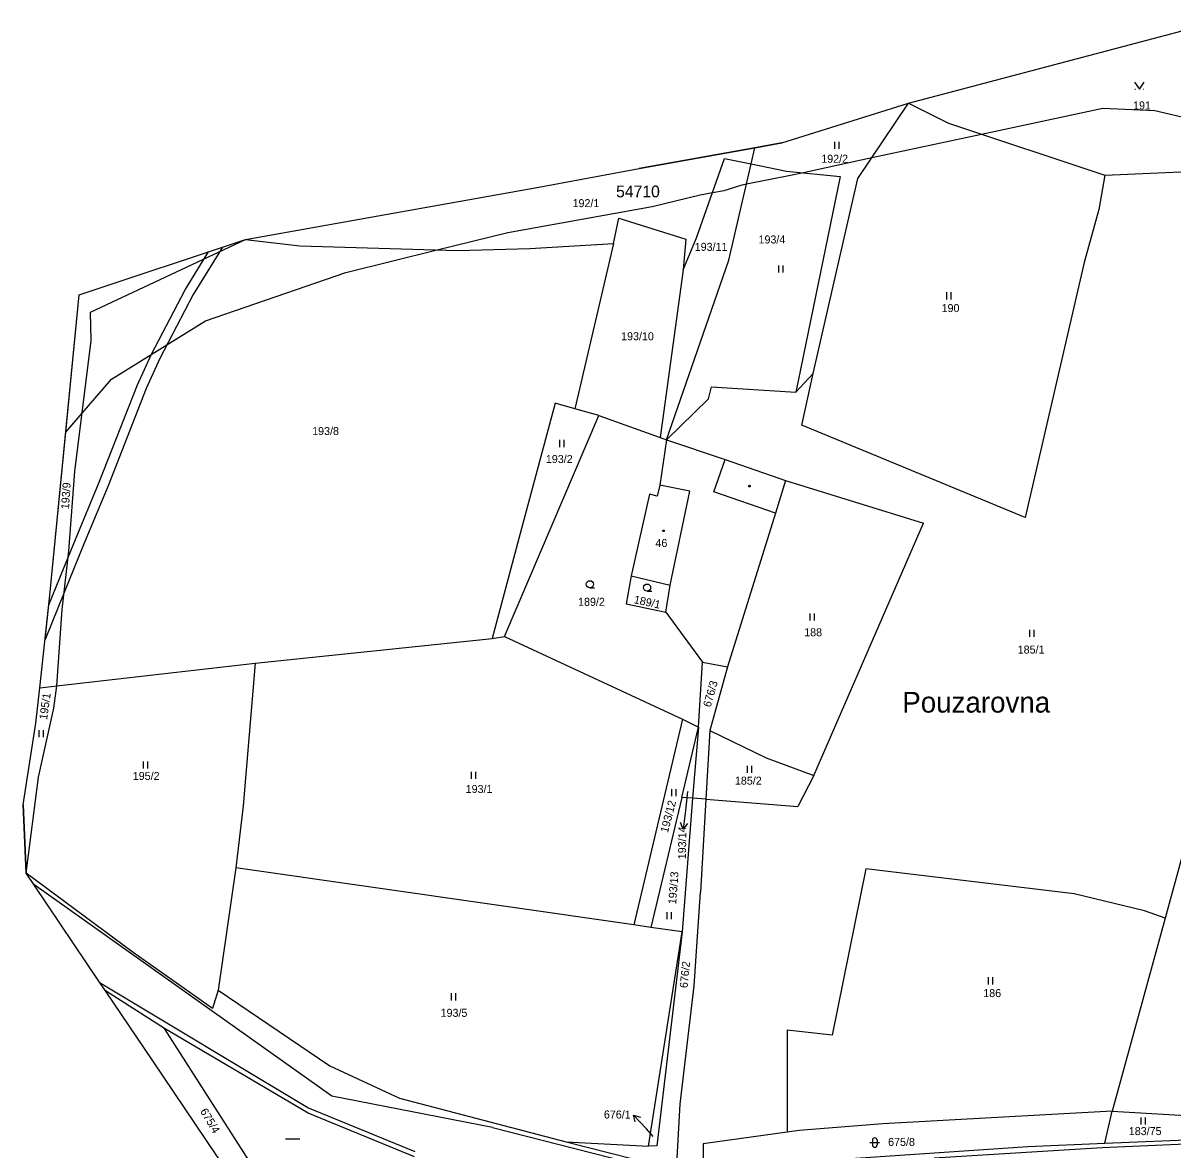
# Model space of a CAD drawing. Extents: x -747333 to -745433, y -1133152 to -1130600.
# Drawn here: x -747275.7 to -747031.5, y -1132285.5 to -1132046.2 of the extents above; entities that cross this region are included whole.
import ezdxf

# ---------------------------------------------------------------- set-up
doc = ezdxf.new("R2010")
doc.units = 0
for name, color, linetype in [('Vrstva 1', 7, 'Continuous'), ('Vrstva 13', 7, 'Continuous'), ('Vrstva 15', 7, 'Continuous'), ('Vrstva 16', 7, 'Continuous'), ('Vrstva 18', 7, 'Continuous'), ('Vrstva 19', 7, 'Continuous'), ('Vrstva 25', 7, 'Continuous'), ('Vrstva 3', 7, 'Continuous'), ('Vrstva 30', 7, 'Continuous'), ('Vrstva 37', 7, 'Continuous'), ('Vrstva 4', 7, 'Continuous'), ('Vrstva 52', 7, 'Continuous'), ('Vrstva 53', 7, 'Continuous'), ('Vrstva 6', 7, 'Continuous')]:
    doc.layers.add(name, color=color, linetype=linetype)

msp = doc.modelspace()

# ---------------------------------------------------------------- linework, layer by layer
at = {"layer": 'Vrstva 1'}
for points in [[(-747098.41, -1132079.17), (-747087.7, -1132063.18)], [(-747087.7, -1132063.18), (-747079.15, -1132067.45)], [(-747079.15, -1132067.45), (-747046.01, -1132078.5)], [(-747121.11, -1132076.06), (-747120.33, -1132072.66)], [(-747125.84, -1132096.55), (-747121.11, -1132076.06)], [(-747046.01, -1132078.5), (-747029.81, -1132077.77)], [(-747107.91, -1132120.57), (-747098.41, -1132079.17)], [(-747139.05, -1132134.66), (-747125.84, -1132096.55)], [(-747111.59, -1132124.55), (-747107.91, -1132120.57)], [(-747130.15, -1132125.95), (-747129.49, -1132123.44)], [(-747129.49, -1132123.44), (-747111.59, -1132124.55)], [(-747162.69, -1132126.85), (-747170.13, -1132154.54)], [(-747158.5, -1132128.05), (-747162.69, -1132126.85)], [(-747139.05, -1132134.66), (-747130.15, -1132125.95)], [(-747153.41, -1132129.5), (-747158.5, -1132128.05)], [(-747173.44, -1132176.4), (-747153.41, -1132129.5)], [(-747153.41, -1132129.5), (-747140.38, -1132134.18)], [(-747140.38, -1132134.18), (-747139.05, -1132134.66)], [(-747139.05, -1132134.66), (-747140.45, -1132144.31)], [(-747139.05, -1132134.66), (-747126.6, -1132138.82)], [(-747126.6, -1132138.82), (-747113.79, -1132143.31)], [(-747113.79, -1132143.31), (-747115.93, -1132150.23)], [(-747113.79, -1132143.31), (-747084.48, -1132152.35)], [(-747142.66, -1132146.22), (-747146.56, -1132163.53)], [(-747141.04, -1132146.66), (-747142.66, -1132146.22)], [(-747140.45, -1132144.31), (-747141.04, -1132146.66)], [(-747115.93, -1132150.23), (-747126.13, -1132182.86)], [(-747107.77, -1132205.94), (-747084.48, -1132152.35)], [(-747170.13, -1132154.54), (-747176.09, -1132176.86)], [(-747146.56, -1132163.53), (-747147.61, -1132169.51)], [(-747146.56, -1132163.53), (-747138.31, -1132165.52)], [(-747139.22, -1132171.24), (-747138.31, -1132165.52)], [(-747014.12, -1132166.6), (-747033.2, -1132236.24)], [(-747147.61, -1132169.51), (-747139.22, -1132171.24)], [(-747139.22, -1132171.24), (-747131.42, -1132181.87)], [(-747226.39, -1132182.08), (-747176.09, -1132176.86)], [(-747176.09, -1132176.86), (-747173.44, -1132176.4)], [(-747173.44, -1132176.4), (-747135.67, -1132194.01)], [(-747268.52, -1132186.91), (-747226.39, -1132182.08)], [(-747226.39, -1132182.08), (-747228.96, -1132212.37)], [(-747132.29, -1132195.65), (-747131.42, -1132181.87)], [(-747131.42, -1132181.87), (-747126.13, -1132182.86)], [(-747126.13, -1132182.86), (-747129.83, -1132196.35)], [(-747272.17, -1132187.34), (-747268.52, -1132186.91)], [(-747135.67, -1132194.01), (-747132.29, -1132195.65)], [(-747132.29, -1132195.65), (-747133.51, -1132210.73)], [(-747129.83, -1132196.35), (-747130.69, -1132210.98)], [(-747129.83, -1132196.35), (-747117.91, -1132202.2)], [(-747117.91, -1132202.2), (-747107.77, -1132205.94)], [(-747228.96, -1132212.37), (-747230.54, -1132225.53)], [(-747133.51, -1132210.73), (-747135.71, -1132239.13)], [(-747130.69, -1132210.98), (-747131.85, -1132230.7)], [(-747252.31, -1132243.54), (-747275.02, -1132226.71)], [(-747230.54, -1132225.53), (-747234.28, -1132251.53)], [(-747145.99, -1132237.68), (-747230.54, -1132225.53)], [(-747133.21, -1132250.62), (-747131.85, -1132230.7)], [(-747033.2, -1132236.24), (-747044.43, -1132277.24)], [(-747142.36, -1132238.19), (-747145.99, -1132237.68)], [(-747142.9, -1132284.67), (-747135.71, -1132239.13)], [(-747135.71, -1132239.13), (-747142.36, -1132238.19)], [(-747235.5, -1132255.39), (-747252.31, -1132243.54)], [(-747234.28, -1132251.53), (-747235.5, -1132255.39)], [(-747234.28, -1132251.53), (-747210.55, -1132267.6)], [(-747136.13, -1132275.75), (-747133.21, -1132250.62)], [(-747245.64, -1132259.69), (-747258.19, -1132251.66)], [(-747224.29, -1132293.07), (-747245.64, -1132259.69)], [(-747215.16, -1132277.65), (-747245.64, -1132259.69)], [(-747210.55, -1132267.6), (-747195.78, -1132274.45)], [(-747195.78, -1132274.45), (-747160.38, -1132283.74)], [(-747136.97, -1132289.67), (-747136.13, -1132275.75)], [(-747192.6, -1132286.93), (-747215.16, -1132277.65)], [(-747044.43, -1132277.24), (-747093.11, -1132279.88)], [(-747046, -1132283.98), (-747044.43, -1132277.24)], [(-747093.11, -1132279.88), (-747110.87, -1132281.31)], [(-747113.45, -1132281.67), (-747131.29, -1132284.16)], [(-747110.87, -1132281.31), (-747113.45, -1132281.67)], [(-747046, -1132283.98), (-747025.21, -1132283.12)], [(-747160.38, -1132283.74), (-747142.9, -1132284.67)], [(-747160.38, -1132283.74), (-747136.97, -1132289.67)], [(-747131.29, -1132284.16), (-747131.25, -1132289.37)], [(-747131.25, -1132289.37), (-747062.36, -1132284.69)], [(-747062.36, -1132284.69), (-747046, -1132283.98)]]:
    msp.add_lwpolyline(points, dxfattribs=at)
at = {"layer": 'Vrstva 13'}
for points in [[(-747087.7, -1132063.18), (-747023.43, -1132046.16)], [(-747114.6, -1132071.63), (-747087.7, -1132063.18)], [(-747120.33, -1132072.66), (-747144.88, -1132077.08)], [(-747114.6, -1132071.63), (-747120.33, -1132072.66)], [(-747166.2, -1132081.01), (-747144.88, -1132077.08)], [(-747228.47, -1132092.15), (-747166.2, -1132081.01)], [(-747263.75, -1132103.85), (-747228.47, -1132092.15)], [(-747269.98, -1132167.65), (-747263.75, -1132103.85)], [(-747272.17, -1132187.34), (-747269.98, -1132167.65)], [(-747273, -1132194.85), (-747272.17, -1132187.34)], [(-747275.71, -1132212.14), (-747273, -1132194.85)], [(-747275.71, -1132212.14), (-747275.02, -1132226.71)], [(-747273.4, -1132229.11), (-747275.02, -1132226.71)], [(-747259.29, -1132250.03), (-747273.4, -1132229.11)], [(-747258.19, -1132251.66), (-747259.29, -1132250.03)], [(-747248.16, -1132266.52), (-747258.19, -1132251.66)], [(-747230, -1132293.43), (-747248.16, -1132266.52)]]:
    msp.add_lwpolyline(points, dxfattribs=at)
at = {"layer": 'Vrstva 16'}
for p, q in [((-747134.630605, -1132216.109137), (-747135.52736, -1132217.312603)), ((-747145.716613, -1132279.495341), (-747146.041489, -1132278.030092))]:
    msp.add_line(p, q, dxfattribs=at)
for points in [[(-747134.59, -1132209.35), (-747135.06, -1132213.34)], [(-747135.06, -1132213.34), (-747135.52736, -1132217.312603), (-747136.120331, -1132215.933877)], [(-747143.34, -1132280.98), (-747146.041489, -1132278.030092), (-747144.610397, -1132278.482283)], [(-747141.89, -1132282.57), (-747143.34, -1132280.98)]]:
    msp.add_lwpolyline(points, dxfattribs=at)
at = {"layer": 'Vrstva 25'}
for p, q in [((-747039.6, -1132060.23), (-747039.5, -1132060.23)), ((-747037.8, -1132060.23), (-747037.7, -1132060.23)), ((-747103.37, -1132071.38), (-747103.37, -1132072.88)), ((-747102.37, -1132072.88), (-747102.37, -1132071.38)), ((-747115.29, -1132097.63), (-747115.29, -1132099.13)), ((-747114.29, -1132099.13), (-747114.29, -1132097.63)), ((-747079.6, -1132103.34), (-747079.6, -1132104.84)), ((-747078.6, -1132104.84), (-747078.6, -1132103.34)), ((-747161.79, -1132134.7), (-747161.79, -1132136.2)), ((-747160.79, -1132136.2), (-747160.79, -1132134.7)), ((-747155.34, -1132166.08), (-747154.34, -1132166.08)), ((-747143.18, -1132166.78), (-747142.18, -1132166.78)), ((-747108.62, -1132171.56), (-747108.62, -1132173.06)), ((-747107.62, -1132173.06), (-747107.62, -1132171.56)), ((-747061.97, -1132174.98), (-747061.97, -1132176.48)), ((-747060.97, -1132176.48), (-747060.97, -1132174.98)), ((-747272.33, -1132196.31), (-747272.33, -1132197.81)), ((-747271.33, -1132197.81), (-747271.33, -1132196.31)), ((-747250.17, -1132202.95), (-747250.17, -1132204.45)), ((-747249.17, -1132204.45), (-747249.17, -1132202.95)), ((-747180.56, -1132205.14), (-747180.56, -1132206.64)), ((-747179.56, -1132206.64), (-747179.56, -1132205.14)), ((-747121.91, -1132203.86), (-747121.91, -1132205.36)), ((-747120.91, -1132205.36), (-747120.91, -1132203.86)), ((-747137.99, -1132208.83), (-747137.99, -1132210.33)), ((-747136.99, -1132210.33), (-747136.99, -1132208.83)), ((-747138.97, -1132234.97), (-747138.97, -1132236.47)), ((-747137.97, -1132236.47), (-747137.97, -1132234.97)), ((-747070.75, -1132248.79), (-747070.75, -1132250.29)), ((-747069.75, -1132250.29), (-747069.75, -1132248.79)), ((-747184.81, -1132252.19), (-747184.81, -1132253.69)), ((-747183.81, -1132253.69), (-747183.81, -1132252.19)), ((-747038.34, -1132278.56), (-747038.34, -1132280.06)), ((-747037.34, -1132280.06), (-747037.34, -1132278.56)), ((-747219.94, -1132283.08), (-747216.94, -1132283.08)), ((-747095.85, -1132283.88), (-747093.85, -1132283.88)), ((-747095.35, -1132283.38), (-747095.35, -1132284.38)), ((-747094.35, -1132283.38), (-747094.35, -1132284.38))]:
    msp.add_line(p, q, dxfattribs=at)
msp.add_lwpolyline([(-747039.65, -1132058.73), (-747038.65, -1132060.23), (-747037.65, -1132058.73)], dxfattribs=at)
for centre, radius in [((-747121.45, -1132144.49), 0.174503), ((-747139.71, -1132153.99), 0.174503), ((-747155.34, -1132165.33), 0.75), ((-747143.18, -1132166.03), 0.75)]:
    msp.add_circle(centre, radius, dxfattribs=at)
for centre, start, end in [((-747094.85, -1132283.38), 0, 180), ((-747094.85, -1132284.38), 180, 0)]:
    msp.add_arc(centre, 0.5, start, end, dxfattribs=at)
at = {"layer": 'Vrstva 3'}
for points in [[(-747142.66, -1132146.22), (-747146.56, -1132163.53)], [(-747141.04, -1132146.66), (-747142.66, -1132146.22)], [(-747140.45, -1132144.31), (-747141.04, -1132146.66)], [(-747134.12, -1132145.56), (-747140.45, -1132144.31)], [(-747138.31, -1132165.52), (-747134.12, -1132145.56)], [(-747146.56, -1132163.53), (-747138.31, -1132165.52)]]:
    msp.add_lwpolyline(points, dxfattribs=at)
at = {"layer": 'Vrstva 30'}
for p, q in [((-747233.91, -1132094.7), (-747239.54, -1132103.82)), ((-747241.28, -1132102.83), (-747237.22, -1132096.25)), ((-747248.42, -1132116.5), (-747241.28, -1132102.83)), ((-747239.54, -1132103.82), (-747246.62, -1132117.38)), ((-747251.37, -1132122.97), (-747248.42, -1132116.5)), ((-747246.62, -1132117.38), (-747249.53, -1132123.75)), ((-747259.51, -1132143.68), (-747251.37, -1132122.97)), ((-747249.53, -1132123.75), (-747257.65, -1132144.43)), ((-747264.58, -1132155.85), (-747259.51, -1132143.68)), ((-747257.65, -1132144.43), (-747262.73, -1132156.61)), ((-747266.17, -1132159.76), (-747264.58, -1132155.85)), ((-747262.73, -1132156.61), (-747266.97, -1132167.07))]:
    msp.add_line(p, q, dxfattribs=at)
for points in [[(-747237.22, -1132096.25), (-747236.29, -1132094.75), (-747233.33, -1132093.76), (-747233.91, -1132094.7)], [(-747266.97, -1132167.07), (-747271.03, -1132177.08), (-747270.21, -1132169.72), (-747266.17, -1132159.76)]]:
    msp.add_lwpolyline(points, dxfattribs=at)
at = {"layer": 'Vrstva 37'}
msp.add_circle((-747139.71, -1132153.99), 0.174503, dxfattribs=at)
at = {"layer": 'Vrstva 4'}
for points in [[(-747129.04, -1132145.74), (-747126.6, -1132138.82)], [(-747134.12, -1132145.56), (-747140.45, -1132144.31)], [(-747138.31, -1132165.52), (-747134.12, -1132145.56)], [(-747115.93, -1132150.23), (-747129.04, -1132145.74)], [(-747210.12, -1132274.02), (-747273.4, -1132229.11)], [(-747215.24, -1132276.52), (-747259.29, -1132250.03)], [(-747175.98, -1132280.66), (-747210.12, -1132274.02)], [(-747192.4, -1132285.87), (-747215.24, -1132276.52)], [(-747175.98, -1132280.66), (-747136.87, -1132290.65)], [(-747046.57, -1132284.9), (-746994.84, -1132282.65)], [(-747082.22, -1132287.12), (-747046.57, -1132284.9)]]:
    msp.add_lwpolyline(points, dxfattribs=at)
at = {"layer": 'Vrstva 52'}
for points in [[(-747266.6, -1132133.02), (-747263.75, -1132103.85), (-747228.47, -1132092.15), (-747166.2, -1132081.01), (-747144.88, -1132077.08), (-747120.33, -1132072.66), (-747114.6, -1132071.63), (-747087.7, -1132063.18), (-747023.43, -1132046.16), (-747003.44, -1132051.26)], [(-747266.6, -1132133.02), (-747263.16, -1132129.01), (-747256.94, -1132121.75), (-747236.94, -1132109.37), (-747207.19, -1132099.13), (-747187.76, -1132094.33), (-747172.75, -1132090.63), (-747142.12, -1132085.12), (-747131.94, -1132082.63), (-747129.3, -1132082.17), (-747126.81, -1132081.75), (-747123, -1132080.5), (-747122.09, -1132080.32), (-747112.38, -1132078.38), (-747110.32, -1132077.94), (-747095.45, -1132074.75), (-747072.2, -1132069.77), (-747046.44, -1132064.25), (-747035.38, -1132064.75), (-747027.53, -1132066.56), (-747024.56, -1132067.25)], [(-747230, -1132293.43), (-747248.16, -1132266.52), (-747258.19, -1132251.66), (-747259.29, -1132250.03), (-747273.4, -1132229.11), (-747275.02, -1132226.71), (-747275.71, -1132212.14), (-747273, -1132194.85), (-747272.17, -1132187.34), (-747269.98, -1132167.65), (-747266.6, -1132133.02)]]:
    msp.add_lwpolyline(points, dxfattribs=at)
at = {"layer": 'Vrstva 6'}
for points in [[(-747132.7, -1132091.74), (-747126.71, -1132074.9)], [(-747126.71, -1132074.9), (-747121.11, -1132076.06)], [(-747121.11, -1132076.06), (-747113.58, -1132077.61)], [(-747113.58, -1132077.61), (-747102.16, -1132078.75)], [(-747102.16, -1132078.75), (-747111.59, -1132124.55)], [(-747046.01, -1132078.5), (-747047.24, -1132085.76)], [(-747150.29, -1132092.96), (-747149.15, -1132087.61)], [(-747149.15, -1132087.61), (-747134.95, -1132092.03)], [(-747047.24, -1132085.76), (-747050.38, -1132097.04)], [(-747261.41, -1132107.59), (-747228.47, -1132092.15)], [(-747228.47, -1132092.15), (-747216.89, -1132093.46)], [(-747135.55, -1132098.59), (-747132.7, -1132091.74)], [(-747134.95, -1132092.03), (-747135.55, -1132098.59)], [(-747216.89, -1132093.46), (-747183.35, -1132094.46)], [(-747183.35, -1132094.46), (-747168.05, -1132094.03)], [(-747168.05, -1132094.03), (-747150.29, -1132092.96)], [(-747150.29, -1132092.96), (-747158.5, -1132128.05)], [(-747050.38, -1132097.04), (-747062.93, -1132151.14)], [(-747135.55, -1132098.59), (-747140.38, -1132134.18)], [(-747261.26, -1132113.58), (-747261.41, -1132107.59)], [(-747264.69, -1132141.42), (-747261.26, -1132113.58)], [(-747110.31, -1132131.58), (-747107.91, -1132120.57)], [(-747062.93, -1132151.14), (-747110.31, -1132131.58)], [(-747266.01, -1132158.33), (-747264.69, -1132141.42)], [(-747267.37, -1132170.68), (-747266.01, -1132158.33)], [(-747268.52, -1132186.91), (-747267.37, -1132170.68)], [(-747269.15, -1132191.66), (-747268.52, -1132186.91)], [(-747272.43, -1132206.29), (-747269.15, -1132191.66)], [(-747135.67, -1132194.01), (-747145.99, -1132237.68)], [(-747135.81, -1132210.59), (-747132.29, -1132195.65)], [(-747275.02, -1132226.71), (-747272.43, -1132206.29)], [(-747107.77, -1132205.94), (-747111.16, -1132212.52)], [(-747135.81, -1132210.59), (-747142.36, -1132238.19)], [(-747133.51, -1132210.73), (-747135.81, -1132210.59)], [(-747130.69, -1132210.98), (-747133.51, -1132210.73)], [(-747130.69, -1132210.98), (-747111.16, -1132212.52)], [(-747096.75, -1132225.79), (-747103.89, -1132261.04)], [(-747052.52, -1132231.07), (-747096.75, -1132225.79)], [(-747037.53, -1132234.64), (-747052.52, -1132231.07)], [(-747033.2, -1132236.24), (-747037.53, -1132234.64)], [(-747135.71, -1132239.13), (-747141.12, -1132284.6)], [(-747103.89, -1132261.04), (-747113.45, -1132260.04)], [(-747113.45, -1132260.04), (-747113.45, -1132281.67)], [(-747044.43, -1132277.24), (-747023.94, -1132278.4)], [(-747141.12, -1132284.6), (-747142.9, -1132284.67)]]:
    msp.add_lwpolyline(points, dxfattribs=at)

# ---------------------------------------------------------------- texts
at = {"layer": 'Vrstva 15'}
msp.add_text('Pouzarovna', height=4.4, dxfattribs=at).set_placement((-747088.994848, -1132192.58))
at = {"layer": 'Vrstva 16'}
msp.add_text('193/14', height=1.7, rotation=89.44551, dxfattribs=at).set_placement((-747134.924269, -1132223.728954))
msp.add_text('676/1', height=1.7, dxfattribs=at).set_placement((-747152.355352, -1132278.77))
at = {"layer": 'Vrstva 18'}
for s, height, p in [('191', 1.7, (-747039.98, -1132064.51)), ('192/2', 1.7, (-747106.2, -1132075.83)), ('192/1', 1.7, (-747159.01, -1132085.26)), ('193/11', 1.7, (-747133.07, -1132094.54)), ('193/4', 1.7, (-747119.52, -1132092.97)), ('190', 1.7, (-747080.64, -1132107.54)), ('193/10', 1.7, (-747148.7, -1132113.52)), ('193/8', 1.7, (-747214.31, -1132133.65)), ('193/2', 1.7, (-747164.68, -1132139.59)), ('189/2', 1.7, (-747157.84, -1132169.91)), ('188', 1.7, (-747109.82, -1132176.38)), ('185/1', 1.7, (-747064.48, -1132180.05)), ('195/2', 1.7, (-747252.4, -1132206.88)), ('185/2', 1.7, (-747124.53, -1132207.88)), ('193/1', 1.7, (-747181.71, -1132209.65)), ('193/14', 0.1, (-747134.59, -1132209.35)), ('186', 1.7, (-747071.79, -1132252.99)), ('193/5', 1.7, (-747187.03, -1132257.18)), ('183/75', 1.7, (-747040.89, -1132282.29)), ('675/8', 1.7, (-747092, -1132284.59))]:
    msp.add_text(s, height=height, dxfattribs=at).set_placement(p)
for s, height, rotation, p in [('193/9', 1.7, 86.25699, (-747265.95, -1132149.45)), ('189/1', 1.7, 347.83614, (-747146.1, -1132169.34)), ('676/3', 1.7, 74.05461, (-747129.71, -1132191.56)), ('195/1', 1.7, 82.03041, (-747270.6, -1132194.17)), ('193/12', 1.7, 75.36618, (-747138.77, -1132218.22)), ('193/13', 1.7, 85.71087, (-747137.02, -1132233.33)), ('676/2', 1.7, 84.32262, (-747134.59, -1132251.14)), ('675/4', 1.7, 300.79494, (-747238.17, -1132277.22)), ('676/1', 0.1, 80.23824, (-747141.89, -1132282.57))]:
    msp.add_text(s, height=height, rotation=rotation, dxfattribs=at).set_placement(p)
at = {"layer": 'Vrstva 19'}
msp.add_text('46', height=1.7, dxfattribs=at).set_placement((-747141.41, -1132157.42))
at = {"layer": 'Vrstva 53'}
msp.add_text('54710', height=2.5, dxfattribs=at).set_placement((-747149.770311, -1132083.17))

doc.saveas('drawing.dxf')
